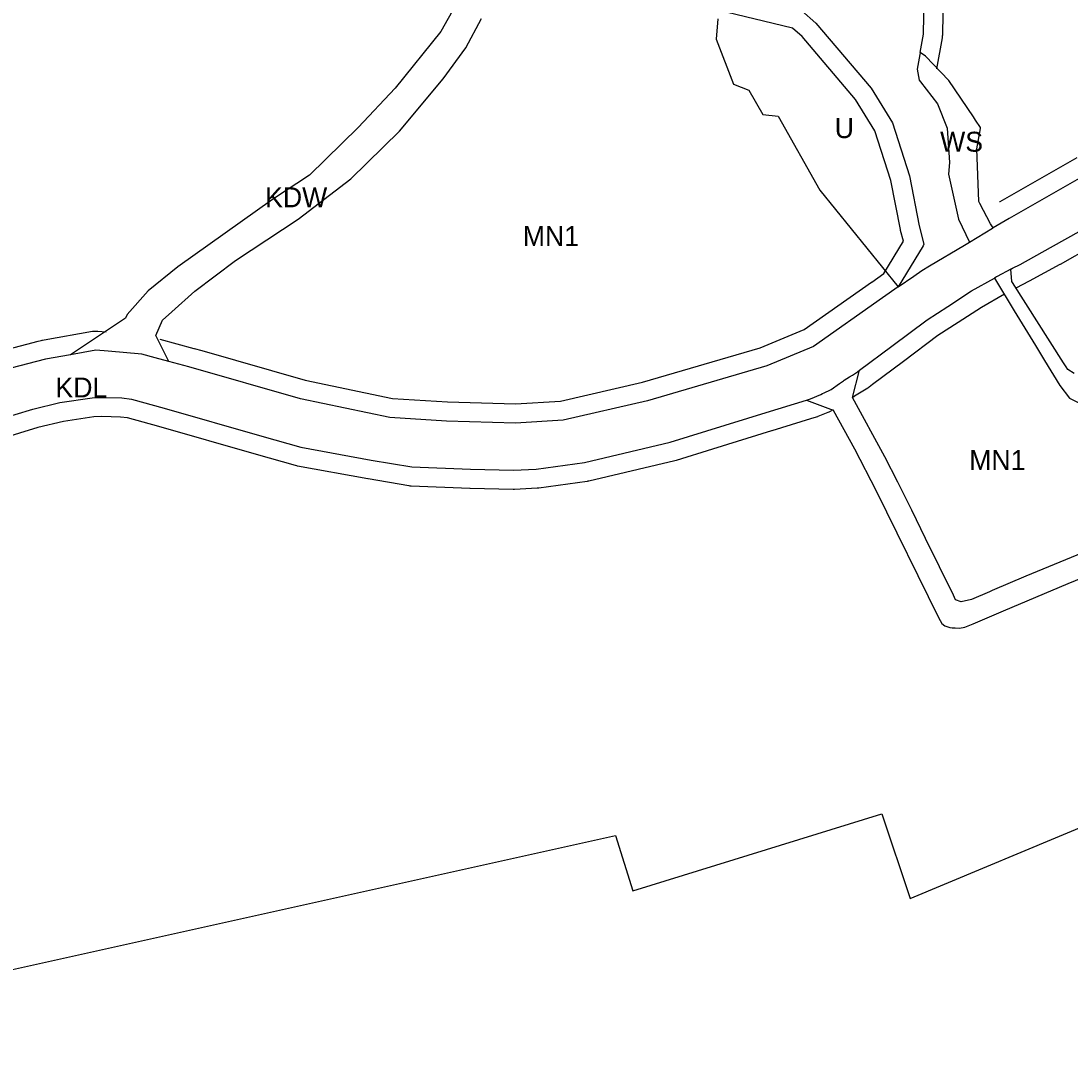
# Model space of a CAD drawing. Extents: x 7435758 to 7439981, y 5550649 to 5554049.
# Drawn here: x 7437107.4 to 7437381.1, y 5551399.2 to 5551668.8 of the extents above; entities that cross this region are included whole.
import ezdxf

# ---------------------------------------------------------------- set-up
doc = ezdxf.new("R2010")
doc.units = 0
for name, color, linetype in [('linie_rozgraniczające', 7, 'Continuous'), ('linie_zabudowy_nieprzekraczalne', 7, 'Continuous'), ('oznaczenia_przeznaczen', 7, 'Continuous')]:
    doc.layers.add(name, color=color, linetype=linetype)

msp = doc.modelspace()

# ---------------------------------------------------------------- linework, layer by layer
at = {"layer": 'linie_rozgraniczające'}
for p, q in [((7437342.85, 5551665.33), (7437343.37, 5551696.97)), ((7437224.64, 5551679.82), (7437216.9, 5551666.02)), ((7437310.98, 5551671.49), (7437314.72, 5551668.25)), ((7437223.43, 5551661.75), (7437227.53, 5551669.44)), ((7437289.18, 5551669.33), (7437288.76, 5551664.07)), ((7437216.9, 5551666.02), (7437205.05, 5551651.28)), ((7437314.72, 5551668.25), (7437329.19, 5551651.22)), ((7437288.76, 5551664.07), (7437293.23, 5551652.27)), ((7437341.98, 5551660.56), (7437342.85, 5551665.33)), ((7437217.53, 5551653.73), (7437223.43, 5551661.75)), ((7437341.98, 5551660.56), (7437341.89, 5551660.07)), ((7437343.36, 5551659.6), (7437341.98, 5551660.56)), ((7437341.89, 5551660.07), (7437341.19, 5551656.23)), ((7437349.43, 5551653.22), (7437343.36, 5551659.6)), ((7437341.19, 5551656.23), (7437341.73, 5551653.37)), ((7437206.16, 5551640.05), (7437217.53, 5551653.73)), ((7437293.23, 5551652.27), (7437297.28, 5551650.76)), ((7437341.73, 5551653.37), (7437342.07, 5551652.93)), ((7437342.07, 5551652.93), (7437342.09, 5551652.9)), ((7437342.09, 5551652.9), (7437346.45, 5551647.18)), ((7437355.85, 5551643.78), (7437349.43, 5551653.22)), ((7437205.05, 5551651.28), (7437195.36, 5551641.03)), ((7437297.28, 5551650.76), (7437300.9, 5551644.39)), ((7437329.19, 5551651.22), (7437334.75, 5551642.19)), ((7437346.45, 5551647.18), (7437349.04, 5551640.83)), ((7437300.9, 5551644.39), (7437304.91, 5551643.93)), ((7437304.91, 5551643.93), (7437315.78, 5551624.62)), ((7437334.75, 5551642.19), (7437339.15, 5551628.36)), ((7437356.44, 5551642.91), (7437355.85, 5551643.78)), ((7437357.73, 5551641.02), (7437356.44, 5551642.91)), ((7437195.36, 5551641.03), (7437182.64, 5551628.59)), ((7437193.44, 5551627.6), (7437206.16, 5551640.05)), ((7437349.04, 5551640.83), (7437349.58, 5551631.89)), ((7437356.75, 5551635.42), (7437357.68, 5551640.73)), ((7437357.68, 5551640.73), (7437357.73, 5551641.02)), ((7437357.3, 5551621.65), (7437356.75, 5551635.42)), ((7437349.58, 5551631.89), (7437349.38, 5551628.79)), ((7437182.64, 5551628.59), (7437173.04, 5551622.24)), ((7437179.73, 5551617.06), (7437193.44, 5551627.6)), ((7437339.15, 5551628.36), (7437341.71, 5551615.37)), ((7437349.38, 5551628.79), (7437352.01, 5551617.11)), ((7437385.3, 5551628.76), (7437365.21, 5551617.29)), ((7437173.04, 5551622.24), (7437148.34, 5551604.64)), ((7437315.78, 5551624.62), (7437336.26, 5551599.38)), ((7437357.55, 5551621.19), (7437357.3, 5551621.65)), ((7437360.31, 5551615.9), (7437357.55, 5551621.19)), ((7437163.32, 5551606.28), (7437179.73, 5551617.06)), ((7437352.01, 5551617.11), (7437354.83, 5551611.09)), ((7437365.21, 5551617.29), (7437361.02, 5551614.79)), ((7437341.71, 5551615.37), (7437342.95, 5551610.56)), ((7437354.83, 5551611.09), (7437360.88, 5551614.71)), ((7437361.02, 5551614.79), (7437360.31, 5551615.9)), ((7437360.88, 5551614.71), (7437361.02, 5551614.79)), ((7437375.99, 5551609.64), (7437384.27, 5551614.31)), ((7437353.54, 5551610.32), (7437354.83, 5551611.09)), ((7437342.73, 5551610.16), (7437336.26, 5551599.38)), ((7437342.95, 5551610.56), (7437342.73, 5551610.16)), ((7437344.42, 5551604.87), (7437353.54, 5551610.32)), ((7437368.02, 5551605.29), (7437375.99, 5551609.64)), ((7437152.75, 5551598.33), (7437163.32, 5551606.28)), ((7437148.34, 5551604.64), (7437140.56, 5551598.36)), ((7437340.3, 5551602.2), (7437342.42, 5551603.68)), ((7437342.42, 5551603.68), (7437344.42, 5551604.87)), ((7437365.63, 5551604.02), (7437362.07, 5551602.11)), ((7437365.89, 5551600.84), (7437365.63, 5551604.02)), ((7437365.63, 5551604.02), (7437365.64, 5551604.02)), ((7437365.64, 5551604.02), (7437366.06, 5551604.25)), ((7437366.06, 5551604.25), (7437368.02, 5551605.29)), ((7437336.26, 5551599.38), (7437340.3, 5551602.2)), ((7437355.37, 5551598.35), (7437361.33, 5551601.7)), ((7437361.88, 5551602.01), (7437361.33, 5551601.7)), ((7437361.33, 5551601.7), (7437366.52, 5551593.17)), ((7437362.07, 5551602.11), (7437361.88, 5551602.01)), ((7437366.07, 5551600.57), (7437365.89, 5551600.84)), ((7437379.39, 5551579.55), (7437366.07, 5551600.57)), ((7437140.56, 5551598.36), (7437135.1, 5551592.17)), ((7437146.74, 5551592.9), (7437152.75, 5551598.33)), ((7437336.26, 5551599.38), (7437332.17, 5551596.54)), ((7437349.17, 5551594.32), (7437355.37, 5551598.35)), ((7437332.17, 5551596.54), (7437314.16, 5551583.88)), ((7437135.1, 5551592.17), (7437134.63, 5551591.25)), ((7437144.31, 5551590.71), (7437146.74, 5551592.9)), ((7437343.75, 5551590.85), (7437349.17, 5551594.32)), ((7437366.52, 5551593.17), (7437366.52, 5551593.17)), ((7437366.52, 5551593.17), (7437372.04, 5551584.11)), ((7437134.63, 5551591.25), (7437120.27, 5551581.71)), ((7437142.54, 5551586.7), (7437144.31, 5551590.71)), ((7437334.59, 5551583.97), (7437343.75, 5551590.85)), ((7437146, 5551579.94), (7437142.54, 5551586.7)), ((7437314.16, 5551583.88), (7437301.93, 5551578.81)), ((7437326.16, 5551577.64), (7437334.59, 5551583.97)), ((7437372.04, 5551584.11), (7437374.39, 5551580.23)), ((7437120.27, 5551581.71), (7437113.83, 5551580.57)), ((7437126.93, 5551582.88), (7437120.27, 5551581.71)), ((7437130.14, 5551582.6), (7437126.93, 5551582.88)), ((7437138.9, 5551581.84), (7437130.14, 5551582.6)), ((7437142.42, 5551580.9), (7437138.9, 5551581.84)), ((7437146, 5551579.94), (7437142.42, 5551580.9)), ((7437113.83, 5551580.57), (7437104.79, 5551578.17)), ((7437151.21, 5551578.54), (7437146, 5551579.94)), ((7437180.35, 5551570.2), (7437151.21, 5551578.54)), ((7437301.93, 5551578.81), (7437270.84, 5551569.69)), ((7437374.39, 5551580.23), (7437378.36, 5551573.71)), ((7437380.02, 5551578.55), (7437379.39, 5551579.55)), ((7437380.45, 5551577.89), (7437380.02, 5551578.55)), ((7437322.12, 5551575.04), (7437323.49, 5551575.9)), ((7437323.49, 5551575.9), (7437324.29, 5551576.4)), ((7437324.29, 5551576.4), (7437325.13, 5551576.93)), ((7437324.31, 5551570.54), (7437326.16, 5551577.64)), ((7437325.13, 5551576.93), (7437325.63, 5551577.24)), ((7437325.63, 5551577.24), (7437326.16, 5551577.64)), ((7437382.18, 5551576.79), (7437380.45, 5551577.89)), ((7437318.02, 5551572.31), (7437318.72, 5551572.66)), ((7437318.72, 5551572.66), (7437320.93, 5551574.21)), ((7437320.93, 5551574.21), (7437321.93, 5551574.91)), ((7437321.93, 5551574.91), (7437322.12, 5551575.04)), ((7437378.36, 5551573.71), (7437380.95, 5551570.4)), ((7437117.56, 5551569.22), (7437125.97, 5551570.47)), ((7437125.97, 5551570.47), (7437128.49, 5551570.57)), ((7437128.49, 5551570.57), (7437133.74, 5551570.44)), ((7437133.74, 5551570.44), (7437136.2, 5551570.12)), ((7437136.2, 5551570.12), (7437144.72, 5551567.77)), ((7437203.64, 5551565.31), (7437180.35, 5551570.2)), ((7437312.34, 5551569.89), (7437313.36, 5551570.21)), ((7437313.36, 5551570.21), (7437316.05, 5551571.3)), ((7437316.05, 5551571.3), (7437316.53, 5551571.55)), ((7437316.53, 5551571.55), (7437316.89, 5551571.73)), ((7437316.89, 5551571.73), (7437317.46, 5551572.02)), ((7437317.46, 5551572.02), (7437318.02, 5551572.31)), ((7437332.79, 5551555.04), (7437324.31, 5551570.54)), ((7437380.95, 5551570.4), (7437393.08, 5551564.08)), ((7437100.72, 5551564.52), (7437110.46, 5551567.5)), ((7437110.46, 5551567.5), (7437117.56, 5551569.22)), ((7437144.72, 5551567.77), (7437170.23, 5551560.45)), ((7437270.84, 5551569.69), (7437248.84, 5551564.61)), ((7437301.76, 5551566.59), (7437312.34, 5551569.89)), ((7437312.34, 5551569.89), (7437319.26, 5551567.28)), ((7437319.26, 5551567.28), (7437324.83, 5551557.11)), ((7437218.4, 5551564.39), (7437203.64, 5551565.31)), ((7437248.84, 5551564.61), (7437236.44, 5551563.85)), ((7437286.32, 5551561.87), (7437301.76, 5551566.59)), ((7437236.44, 5551563.85), (7437218.4, 5551564.39)), ((7437276.79, 5551558.9), (7437286.32, 5551561.87)), ((7437170.23, 5551560.45), (7437180.41, 5551557.58)), ((7437180.41, 5551557.58), (7437198.76, 5551554.23)), ((7437254.38, 5551553.62), (7437276.79, 5551558.9)), ((7437324.83, 5551557.11), (7437330.51, 5551546.19)), ((7437198.76, 5551554.23), (7437209.4, 5551552.42)), ((7437241.83, 5551551.89), (7437254.38, 5551553.62)), ((7437336.1, 5551548.42), (7437332.79, 5551555.04)), ((7437209.4, 5551552.42), (7437224.7, 5551551.82)), ((7437224.7, 5551551.82), (7437235.9, 5551551.58)), ((7437235.9, 5551551.58), (7437241.83, 5551551.89)), ((7437339.76, 5551541.13), (7437336.1, 5551548.42)), ((7437330.51, 5551546.19), (7437346.78, 5551513.13)), ((7437418.77, 5551544.23), (7437369.52, 5551523.95)), ((7437343.39, 5551533.72), (7437339.76, 5551541.13)), ((7437350.62, 5551518.94), (7437343.39, 5551533.72)), ((7437369.52, 5551523.95), (7437360.76, 5551520.19)), ((7437380.59, 5551522), (7437384.42, 5551523.61)), ((7437363.69, 5551514.91), (7437380.59, 5551522)), ((7437351.2, 5551517.75), (7437350.62, 5551518.94)), ((7437360.03, 5551519.87), (7437355.36, 5551517.87)), ((7437360.76, 5551520.19), (7437360.03, 5551519.87)), ((7437352.67, 5551517.2), (7437351.2, 5551517.75)), ((7437355.36, 5551517.87), (7437352.67, 5551517.2)), ((7437346.78, 5551513.13), (7437347.62, 5551511.61)), ((7437355.79, 5551511.52), (7437363.69, 5551514.91)), ((7437347.62, 5551511.61), (7437348.36, 5551510.97)), ((7437348.36, 5551510.97), (7437349.71, 5551510.54)), ((7437349.71, 5551510.54), (7437350.29, 5551510.49)), ((7437350.29, 5551510.49), (7437351.14, 5551510.43)), ((7437351.14, 5551510.43), (7437352.21, 5551510.35)), ((7437352.21, 5551510.35), (7437353.61, 5551510.59)), ((7437353.61, 5551510.59), (7437355.79, 5551511.52)), ((7437339.37, 5551439.87), (7437430.62, 5551478.01)), ((7437267.01, 5551441.82), (7437332, 5551461.92)), ((7437332, 5551461.92), (7437339.37, 5551439.87)), ((7437006.21, 5551399.25), (7437262.51, 5551456.29)), ((7437262.51, 5551456.29), (7437267.01, 5551441.82))]:
    msp.add_line(p, q, dxfattribs=at)
at = {"layer": 'linie_zabudowy_nieprzekraczalne'}
for points in [[(7437346.28, 5551656.3), (7437347.77, 5551664.43), (7437347.79, 5551664.55), (7437347.83, 5551664.88), (7437347.85, 5551665.2), (7437347.85, 5551665.25), (7437348.37, 5551696.89), (7437348.37, 5551697), (7437348.27, 5551715.94), (7437351.13, 5551721.28), (7437370.43, 5551732.71), (7437380.41, 5551737), (7437380.65, 5551737.1), (7437380.94, 5551737.25), (7437380.97, 5551737.26), (7437385.32, 5551739.66)], [(7437143.63, 5551585.75), (7437152.51, 5551583.36), (7437152.59, 5551583.34), (7437154.55, 5551582.78), (7437181.55, 5551575.06), (7437204.32, 5551570.28), (7437218.63, 5551569.38), (7437236.36, 5551568.85), (7437248.12, 5551569.57), (7437269.57, 5551574.52), (7437300.27, 5551583.54), (7437311.74, 5551588.29), (7437329.3, 5551600.63), (7437329.32, 5551600.64), (7437332.52, 5551602.87), (7437337.59, 5551611.32), (7437336.87, 5551614.12), (7437336.85, 5551614.19), (7437336.81, 5551614.4), (7437334.3, 5551627.12), (7437330.18, 5551640.09), (7437325.14, 5551648.28), (7437311.16, 5551664.72), (7437308.63, 5551666.91), (7437288.83, 5551671.65)], [(7437382.82, 5551633.1), (7437362.73, 5551621.63), (7437362.65, 5551621.58)], [(7437386.72, 5551609.96), (7437378.45, 5551605.28), (7437378.39, 5551605.25), (7437370.41, 5551600.9), (7437370.38, 5551600.88), (7437366.95, 5551599.05)], [(7437364, 5551597.47), (7437357.96, 5551594.07), (7437351.89, 5551590.13), (7437351.86, 5551590.11), (7437346.6, 5551586.74), (7437337.59, 5551579.97), (7437329.53, 5551573.92), (7437328.63, 5551573.25), (7437328.57, 5551573.2), (7437328.3, 5551573.02), (7437328.29, 5551573.01), (7437324.88, 5551570.87), (7437324.34, 5551570.49)], [(7437104.3, 5551583.22), (7437111.87, 5551585.22), (7437112.65, 5551585.43), (7437112.65, 5551585.43), (7437112.95, 5551585.49), (7437113.03, 5551585.51), (7437113.43, 5551585.58), (7437126.07, 5551587.81), (7437126.09, 5551587.81), (7437126.4, 5551587.85), (7437126.41, 5551587.85), (7437126.7, 5551587.87), (7437126.74, 5551587.88), (7437127.05, 5551587.88), (7437127.06, 5551587.88), (7437127.35, 5551587.86), (7437127.44, 5551587.85), (7437129.58, 5551587.67)], [(7437319.24, 5551567.31), (7437318.32, 5551566.84), (7437318.14, 5551566.76), (7437317.92, 5551566.66), (7437315.24, 5551565.57), (7437315.16, 5551565.54), (7437314.85, 5551565.44), (7437313.32, 5551564.96), (7437303.25, 5551561.82), (7437303.22, 5551561.81), (7437287.79, 5551557.09), (7437278.28, 5551554.13), (7437277.97, 5551554.04), (7437277.94, 5551554.03), (7437255.53, 5551548.75), (7437255.24, 5551548.69), (7437255.07, 5551548.67), (7437242.52, 5551546.93), (7437242.36, 5551546.91), (7437242.09, 5551546.89), (7437236.16, 5551546.58), (7437236.1, 5551546.58), (7437235.79, 5551546.58), (7437224.59, 5551546.82), (7437224.58, 5551546.82), (7437224.51, 5551546.82), (7437209.2, 5551547.43), (7437208.95, 5551547.44), (7437208.62, 5551547.48), (7437208.56, 5551547.49), (7437197.93, 5551549.3), (7437197.87, 5551549.31), (7437179.52, 5551552.66), (7437179.32, 5551552.7), (7437179.05, 5551552.76), (7437168.87, 5551555.64), (7437168.85, 5551555.64), (7437143.37, 5551562.96), (7437135.21, 5551565.2), (7437133.35, 5551565.45), (7437128.52, 5551565.57), (7437126.44, 5551565.49), (7437118.52, 5551564.31), (7437111.79, 5551562.68), (7437102.24, 5551559.75)]]:
    msp.add_lwpolyline(points, dxfattribs=at)

# ---------------------------------------------------------------- texts
at = {"layer": 'oznaczenia_przeznaczen'}
for s, p in [('U', (7437319.67, 5551638.23)), ('WS', (7437347.17, 5551634.68)), ('KDW', (7437171.08, 5551620.18)), ('MN1', (7437238.3, 5551610.07)), ('KDL', (7437116.39, 5551570.56)), ('MN1', (7437354.76, 5551551.62))]:
    msp.add_text(s, height=5.2, dxfattribs=at).set_placement(p)

doc.saveas('drawing.dxf')
